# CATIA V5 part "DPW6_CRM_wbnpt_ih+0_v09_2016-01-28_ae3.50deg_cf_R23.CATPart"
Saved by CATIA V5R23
Part number: DPW6_CRM_wbnpt_ih+0_v09_2016-01-28_ae3
Bounding box of the stored display mesh (mm): x 2349.5 to 66711.883, y -0.001 to 29448.404, z -64.344 to 8715.76
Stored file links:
  C:\Users\mrg\work\AIAA_DPW\DPW6\DLR_meshes\all\3deg50\DPW6_CRM_wbnpt_ih+0_v09_2016-01-28_ae3.50deg_cf_R23.CATPart

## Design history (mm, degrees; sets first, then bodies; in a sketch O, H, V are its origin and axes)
MechanicalRefPlane1 "xy-plane"
MechanicalRefPlane2 "yz-plane"
MechanicalRefPlane3 "zx-plane"
Set1
  DatumSurface1 to DatumSurface3
Body1 (main body)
